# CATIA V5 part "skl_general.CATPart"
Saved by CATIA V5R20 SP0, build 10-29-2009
Part number: skl_general
Bounding box of the stored display mesh (mm): x 0 to 0, y -50 to 580, z -135.197 to 298.759
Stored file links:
  C:\Users\Lambert\Desktop\IAO\skl_general.CATPart
  C:\Users\Lambert\Desktop\IAO\Produit1.CATProduct
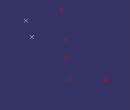
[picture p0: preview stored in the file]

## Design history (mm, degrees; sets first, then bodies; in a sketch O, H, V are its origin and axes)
External parameters (linked from other documents)
  External.AG = 580 mm
  External.AD = 330 mm
  External.DG = 310 mm
  External.BC = 310 mm
  External.DC = 250 mm
  External.BE = 350 mm
  External.CE = 190 mm
  External.EF = 310 mm
  External.GF = 310 mm
Set1
  Point1 "A": (0, 0, 0)
  Plane1 "Plan_Ref": type Offset, RefPlane yz-plane, Offset 0
  Point2 "G": (0, 580 {= External.AG}, 0)
  Circle1: type CtrRad, Start 0, End 180, Center Point1, Support Plane1, Radius 330 {= External.AD}, FirstDirection (0, 1, 0)
  Circle2: type CtrRad, Start 0, End 180, Center Point2, Support Plane1, Radius 310 {= External.DG}, FirstDirection (0, 1, 0)
  Intersect1: ToIntersect1 Circle1, ToIntersect2 Circle2
  Extract1 "D": ExtractElem vertex of Intersect1
  Point3 "B": (0, -50, 86.6025)
  Circle3: type CtrRad, Start 0, End 180, Center Point3, Support Plane1, Radius 310 {= External.BC}, FirstDirection (0, 1, 0)
  Circle4: type CtrRad, Start 0, End 180, Center Extract1, Support Plane1, Radius 250 {= External.DC}, FirstDirection (0, 1, 0)
  Intersect2: ToIntersect1 Circle3, ToIntersect2 Circle4
  Extract2 "C": ExtractElem vertex of Intersect2
  Circle5: type CtrRad, Start 0, End 180, Center Point3, Support Plane1, Radius 350 {= External.BE}, FirstDirection (0, 1, 0)
  Circle6: type CtrRad, Start 0, End 180, Center Extract2, Support Plane1, Radius 190 {= External.CE}, FirstDirection (0, 1, 0)
  Intersect3: ToIntersect1 Circle6, ToIntersect2 Circle5
  Extract3 "E": ExtractElem vertex of Intersect3
  Circle7: type CtrRad, Start 0, End 180, Center Extract3, Support Plane1, Radius 310 {= External.EF}, FirstDirection (0, 1, 0)
  Circle8: type CtrRad, Start 0, End 180, Center Point2, Support Plane1, Radius 310 {= External.GF}, FirstDirection (0, 1, 0)
  Intersect4: ToIntersect1 Circle8, ToIntersect2 Circle7
  Extract4 "F": ExtractElem vertex of Intersect4
Body1 (main body)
